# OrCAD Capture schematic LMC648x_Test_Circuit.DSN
size A; title: LMC6482 CMOS Dual Rail-to-Rail Input and Output Operational; rev: 1.3; note: Datasheet: SNOS674G  EVM: N/A
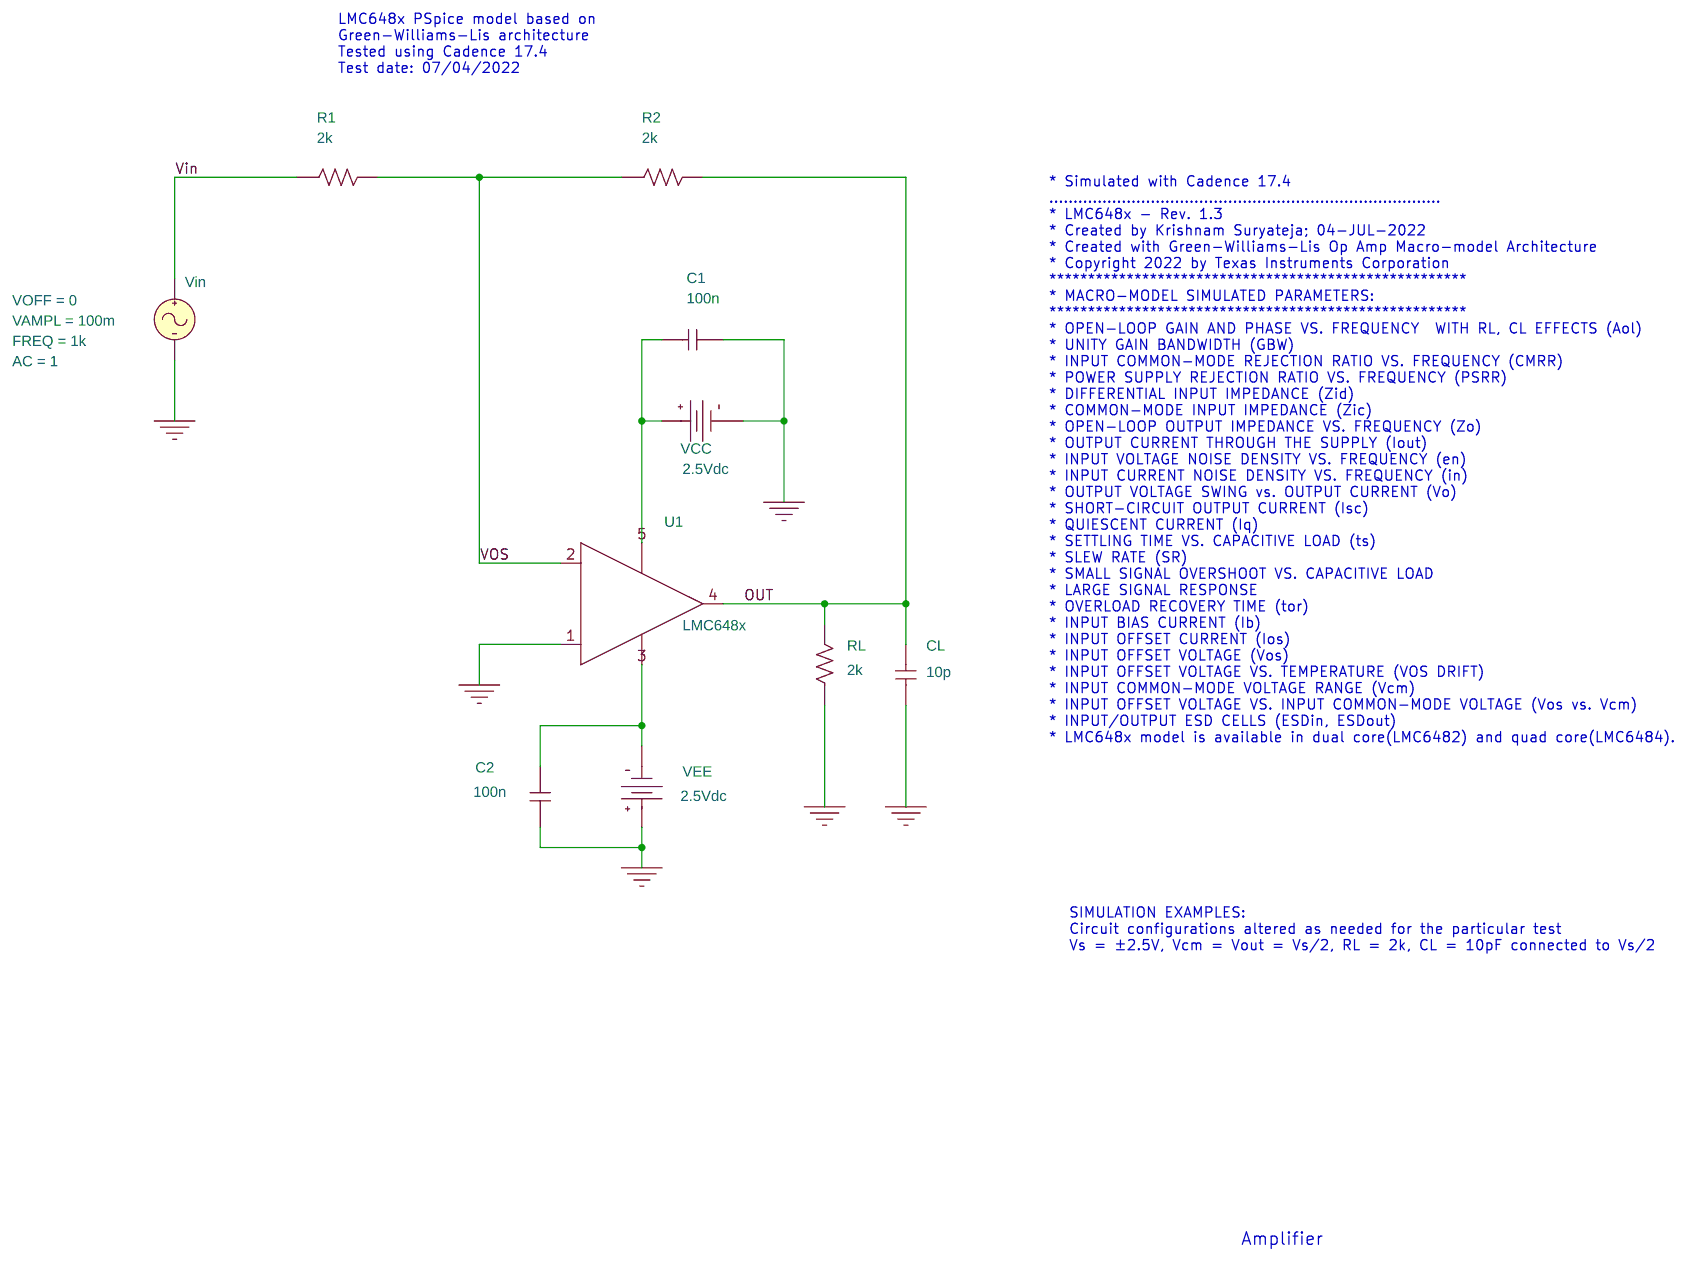
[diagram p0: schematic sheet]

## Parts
C1  100n  [cap196]
C2  100n  [cap196]
CL  10p  [cap196]
R1  2k  [AXRC05]
R2  2k  [AXRC05]
RL  2k  [AXRC05]
U1  LMC648x
VCC  VDC
VEE  VDC
Vin  VSIN

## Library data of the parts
C1 C2 CL = C
R1 R2 RL = R
U1 = LMC648x
VCC VEE = VDC: DC: 2.5Vdc
Vin = VSIN: AC: 1; FREQ: 1k; VAMPL: 100m; VOFF: 0

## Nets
Vin: R1.1 Vin.1(+)
0: C1.2 C2.1 CL.2 RL.1 U1.1(+) VCC.1(-) VEE.0(+) Vin.2(-)
OUT: CL.1 R2.2 RL.2 U1.4(OUT)
VOS: R1.2 R2.1 U1.2(-)
N27303: C1.1 U1.5(V+) VCC.0(+)
N27354: C2.2 U1.3(V-) VEE.1(-)

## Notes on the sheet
- LMC648x PSpice model based on
  Green-Williams-Lis architecture
  Tested using Cadence 17.4
  Test date: 07/04/2022
- * Simulated with Cadence 17.4
  .................................................................................
  * LMC648x - Rev. 1.3
  * Created by Krishnam Suryateja; 04-JUL-2022
  * Created with Green-Williams-Lis Op Amp Macro-model Architecture
  * Copyright 2022 by Texas Instruments Corporation
  ******************************************************
  * MACRO-MODEL SIMULATED PARAMETERS:
  ******************************************************
  * OPEN-LOOP GAIN AND PHASE VS. FREQUENCY  WITH RL, CL EFFECTS (Aol)
  * UNITY GAIN BANDWIDTH (GBW)
  * INPUT COMMON-MODE REJECTION RATIO VS. FREQUENCY (CMRR)
  * POWER SUPPLY REJECTION RATIO VS. FREQUENCY (PSRR)
  * DIFFERENTIAL INPUT IMPEDANCE (Zid)
  * COMMON-MODE INPUT IMPEDANCE (Zic)
  * OPEN-LOOP OUTPUT IMPEDANCE VS. FREQUENCY (Zo)
  * OUTPUT CURRENT THROUGH THE SUPPLY (Iout)
  * INPUT VOLTAGE NOISE DENSITY VS. FREQUENCY (en)
  * INPUT CURRENT NOISE DENSITY VS. FREQUENCY (in)
  * OUTPUT VOLTAGE SWING vs. OUTPUT CURRENT (Vo)
  * SHORT-CIRCUIT OUTPUT CURRENT (Isc)
  * QUIESCENT CURRENT (Iq)
  * SETTLING TIME VS. CAPACITIVE LOAD (ts)
  * SLEW RATE (SR)
  * SMALL SIGNAL OVERSHOOT VS. CAPACITIVE LOAD
  * LARGE SIGNAL RESPONSE
  * OVERLOAD RECOVERY TIME (tor)
  * INPUT BIAS CURRENT (Ib)
  * INPUT OFFSET CURRENT (Ios)
  * INPUT OFFSET VOLTAGE (Vos)
  * INPUT OFFSET VOLTAGE VS. TEMPERATURE (VOS DRIFT)
  * INPUT COMMON-MODE VOLTAGE RANGE (Vcm)
  * INPUT OFFSET VOLTAGE VS. INPUT COMMON-MODE VOLTAGE (Vos vs. Vcm)
  * INPUT/OUTPUT ESD CELLS (ESDin, ESDout)
  * LMC648x model is available in dual core(LMC6482) and quad core(LMC6484).
- SIMULATION EXAMPLES:
  Circuit configurations altered as needed for the particular test
  Vs = ±2.5V, Vcm = Vout = Vs/2, RL = 2k, CL = 10pF connected to Vs/2
- Amplifier
